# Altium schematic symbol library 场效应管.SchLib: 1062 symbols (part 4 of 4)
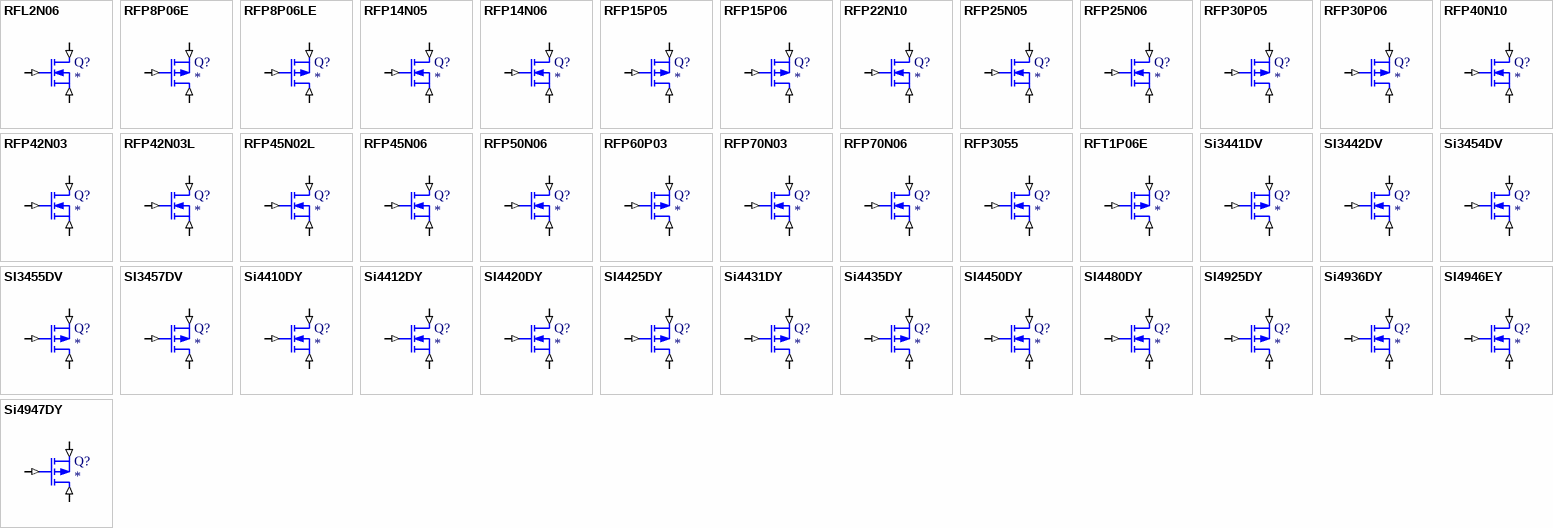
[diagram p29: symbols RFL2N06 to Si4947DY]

## RFP3055
designator Q?
N-Channel MOSFET
simulation model RFP3055 (SUBCKT)
pins: 1 D (in), 2 G (in), 3 S (in)
1 alternate drawing of the same symbol

## RFT1P06E
designator Q?
P-Channel MOSFET
simulation model RFT1P06E (SUBCKT)
pins: 1 D (in), 2 G (in), 3 S (in)
1 alternate drawing of the same symbol

## Si3441DV
designator Q?
P-Channel MOSFET
simulation model Si3441DV (SUBCKT)
pins: 1 D (in), 2 G (in), 3 S (in)
1 alternate drawing of the same symbol

## SI3442DV
designator Q?
N-Channel MOSFET
simulation model SI3442DV (SUBCKT)
pins: 1 D (in), 2 G (in), 3 S (in)
1 alternate drawing of the same symbol

## Si3454DV
designator Q?
N-Channel MOSFET
simulation model Si3454DV (SUBCKT)
pins: 1 D (in), 2 G (in), 3 S (in)
1 alternate drawing of the same symbol

## SI3455DV
designator Q?
P-Channel MOSFET
simulation model SI3455DV (SUBCKT)
pins: 1 D (in), 2 G (in), 3 S (in)
1 alternate drawing of the same symbol

## SI3457DV
designator Q?
P-Channel MOSFET
simulation model SI3457DV (SUBCKT)
pins: 1 D (in), 2 G (in), 3 S (in)
1 alternate drawing of the same symbol

## Si4410DY
designator Q?
N-Channel MOSFET
simulation model Si4410DY (SUBCKT)
pins: 1 D (in), 2 G (in), 3 S (in)
1 alternate drawing of the same symbol

## Si4412DY
designator Q?
N-Channel MOSFET
simulation model Si4412DY (SUBCKT)
pins: 1 D (in), 2 G (in), 3 S (in)
1 alternate drawing of the same symbol

## SI4420DY
designator Q?
N-Channel MOSFET
simulation model SI4420DY (SUBCKT)
pins: 1 D (in), 2 G (in), 3 S (in)
1 alternate drawing of the same symbol

## SI4425DY
designator Q?
P-Channel MOSFET
simulation model SI4425DY (SUBCKT)
pins: 1 D (in), 2 G (in), 3 S (in)
1 alternate drawing of the same symbol

## Si4431DY
designator Q?
P-Channel MOSFET
simulation model Si4431DY (SUBCKT)
pins: 1 D (in), 2 G (in), 3 S (in)
1 alternate drawing of the same symbol

## Si4435DY
designator Q?
P-Channel MOSFET
simulation model Si4435DY (SUBCKT)
pins: 1 D (in), 2 G (in), 3 S (in)
1 alternate drawing of the same symbol

## SI4450DY
designator Q?
N-Channel MOSFET
simulation model SI4450DY (SUBCKT)
pins: 1 D (in), 2 G (in), 3 S (in)
1 alternate drawing of the same symbol

## SI4480DY
designator Q?
N-Channel MOSFET
simulation model SI4480DY (SUBCKT)
pins: 1 D (in), 2 G (in), 3 S (in)
1 alternate drawing of the same symbol

## SI4925DY
designator Q?
P-Channel MOSFET
simulation model SI4925DY (SUBCKT)
pins: 1 D (in), 2 G (in), 3 S (in)
1 alternate drawing of the same symbol

## Si4936DY
designator Q?
N-Channel MOSFET
simulation model Si4936DY (SUBCKT)
pins: 1 D (in), 2 G (in), 3 S (in)
1 alternate drawing of the same symbol

## SI4946EY
designator Q?
N-Channel MOSFET
simulation model SI4946EY (SUBCKT)
pins: 1 D (in), 2 G (in), 3 S (in)
1 alternate drawing of the same symbol

## Si4947DY
designator Q?
P-Channel MOSFET
simulation model Si4947DY (SUBCKT)
pins: 1 D (in), 2 G (in), 3 S (in)
1 alternate drawing of the same symbol

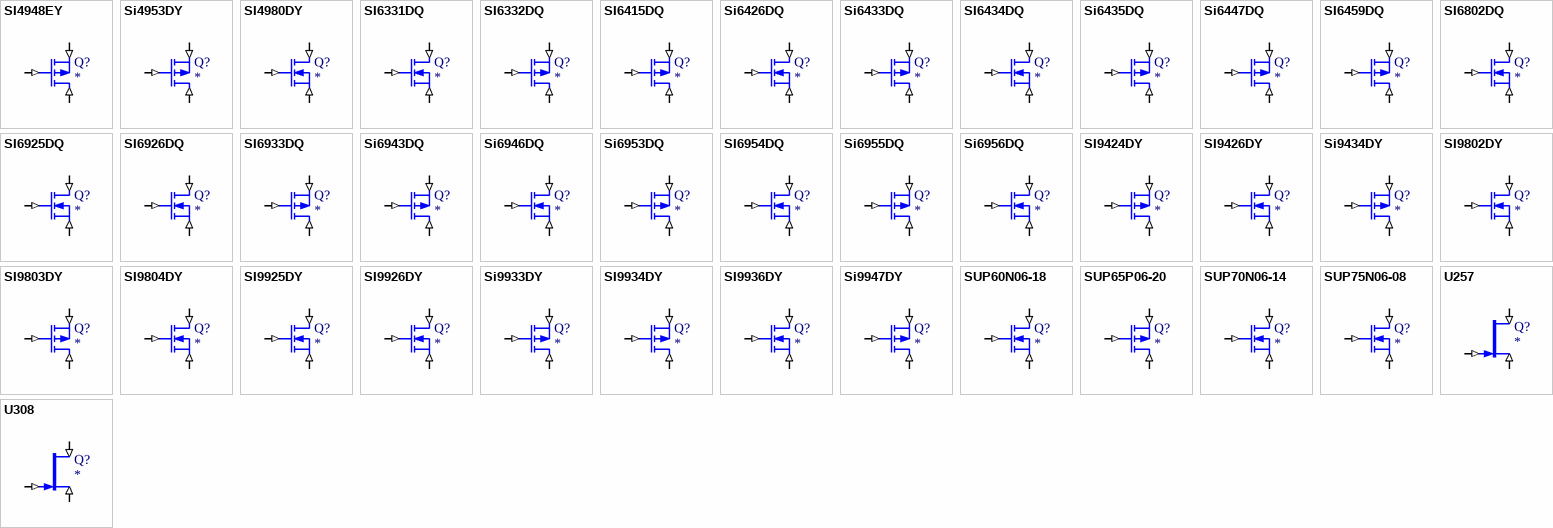
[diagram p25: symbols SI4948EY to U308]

## SI4948EY
designator Q?
P-Channel MOSFET
simulation model SI4948EY (SUBCKT)
pins: 1 D (in), 2 G (in), 3 S (in)
1 alternate drawing of the same symbol

## Si4953DY
designator Q?
P-Channel MOSFET
simulation model Si4953DY (SUBCKT)
pins: 1 D (in), 2 G (in), 3 S (in)
1 alternate drawing of the same symbol

## SI4980DY
designator Q?
N-Channel MOSFET
simulation model SI4980DY (SUBCKT)
pins: 1 D (in), 2 G (in), 3 S (in)
1 alternate drawing of the same symbol

## SI6331DQ
designator Q?
N-Channel MOSFET
simulation model SI6331DQ (SUBCKT)
pins: 1 D (in), 2 G (in), 3 S (in)
1 alternate drawing of the same symbol

## SI6332DQ
designator Q?
P-Channel MOSFET
simulation model SI6332DQ (SUBCKT)
pins: 1 D (in), 2 G (in), 3 S (in)
1 alternate drawing of the same symbol

## SI6415DQ
designator Q?
P-Channel MOSFET
simulation model SI6415DQ (SUBCKT)
pins: 1 D (in), 2 G (in), 3 S (in)
1 alternate drawing of the same symbol

## Si6426DQ
designator Q?
N-Channel MOSFET
simulation model Si6426DQ (SUBCKT)
pins: 1 D (in), 2 G (in), 3 S (in)
1 alternate drawing of the same symbol

## Si6433DQ
designator Q?
P-Channel MOSFET
simulation model Si6433DQ (SUBCKT)
pins: 1 D (in), 2 G (in), 3 S (in)
1 alternate drawing of the same symbol

## SI6434DQ
designator Q?
N-Channel MOSFET
simulation model SI6434DQ (SUBCKT)
pins: 1 D (in), 2 G (in), 3 S (in)
1 alternate drawing of the same symbol

## Si6435DQ
designator Q?
P-Channel MOSFET
simulation model Si6435DQ (SUBCKT)
pins: 1 D (in), 2 G (in), 3 S (in)
1 alternate drawing of the same symbol

## Si6447DQ
designator Q?
P-Channel MOSFET
simulation model Si6447DQ (SUBCKT)
pins: 1 D (in), 2 G (in), 3 S (in)
1 alternate drawing of the same symbol

## SI6459DQ
designator Q?
P-Channel MOSFET
simulation model SI6459DQ (SUBCKT)
pins: 1 D (in), 2 G (in), 3 S (in)
1 alternate drawing of the same symbol

## SI6802DQ
designator Q?
N-Channel MOSFET
simulation model SI6802DQ (SUBCKT)
pins: 1 D (in), 2 G (in), 3 S (in)
1 alternate drawing of the same symbol

## SI6925DQ
designator Q?
N-Channel MOSFET
simulation model SI6925DQ (SUBCKT)
pins: 1 D (in), 2 G (in), 3 S (in)
1 alternate drawing of the same symbol

## SI6926DQ
designator Q?
N-Channel MOSFET
simulation model SI6926DQ (SUBCKT)
pins: 1 D (in), 2 G (in), 3 S (in)
1 alternate drawing of the same symbol

## SI6933DQ
designator Q?
P-Channel MOSFET
simulation model SI6933DQ (SUBCKT)
pins: 1 D (in), 2 G (in), 3 S (in)
1 alternate drawing of the same symbol

## Si6943DQ
designator Q?
P-Channel MOSFET
simulation model Si6943DQ (SUBCKT)
pins: 1 D (in), 2 G (in), 3 S (in)
1 alternate drawing of the same symbol

## Si6946DQ
designator Q?
N-Channel MOSFET
simulation model Si6946DQ (SUBCKT)
pins: 1 D (in), 2 G (in), 3 S (in)
1 alternate drawing of the same symbol

## Si6953DQ
designator Q?
P-Channel MOSFET
simulation model Si6953DQ (SUBCKT)
pins: 1 D (in), 2 G (in), 3 S (in)
1 alternate drawing of the same symbol

## SI6954DQ
designator Q?
N-Channel MOSFET
simulation model SI6954DQ (SUBCKT)
pins: 1 D (in), 2 G (in), 3 S (in)
1 alternate drawing of the same symbol

## Si6955DQ
designator Q?
P-Channel MOSFET
simulation model Si6955DQ (SUBCKT)
pins: 1 D (in), 2 G (in), 3 S (in)
1 alternate drawing of the same symbol

## Si6956DQ
designator Q?
N-Channel MOSFET
simulation model Si6956DQ (SUBCKT)
pins: 1 D (in), 2 G (in), 3 S (in)
1 alternate drawing of the same symbol

## SI9424DY
designator Q?
P-Channel MOSFET
simulation model SI9424DY (SUBCKT)
pins: 1 D (in), 2 G (in), 3 S (in)
1 alternate drawing of the same symbol

## SI9426DY
designator Q?
N-Channel MOSFET
simulation model SI9426DY (SUBCKT)
pins: 1 D (in), 2 G (in), 3 S (in)
1 alternate drawing of the same symbol

## Si9434DY
designator Q?
P-Channel MOSFET
simulation model Si9434DY (SUBCKT)
pins: 1 D (in), 2 G (in), 3 S (in)
1 alternate drawing of the same symbol

## SI9802DY
designator Q?
N-Channel MOSFET
simulation model SI9802DY (SUBCKT)
pins: 1 D (in), 2 G (in), 3 S (in)
1 alternate drawing of the same symbol

## SI9803DY
designator Q?
P-Channel MOSFET
simulation model SI9803DY (SUBCKT)
pins: 1 D (in), 2 G (in), 3 S (in)
1 alternate drawing of the same symbol

## SI9804DY
designator Q?
N-Channel MOSFET
simulation model SI9804DY (SUBCKT)
pins: 1 D (in), 2 G (in), 3 S (in)
1 alternate drawing of the same symbol

## SI9925DY
designator Q?
N-Channel MOSFET
simulation model SI9925DY (SUBCKT)
pins: 1 D (in), 2 G (in), 3 S (in)
1 alternate drawing of the same symbol

## SI9926DY
designator Q?
N-Channel MOSFET
simulation model SI9926DY (SUBCKT)
pins: 1 D (in), 2 G (in), 3 S (in)
1 alternate drawing of the same symbol

## Si9933DY
designator Q?
P-Channel MOSFET
simulation model Si9933DY (SUBCKT)
pins: 1 D (in), 2 G (in), 3 S (in)
1 alternate drawing of the same symbol

## SI9934DY
designator Q?
P-Channel MOSFET
simulation model SI9934DY (SUBCKT)
pins: 1 D (in), 2 G (in), 3 S (in)
1 alternate drawing of the same symbol

## SI9936DY
designator Q?
N-Channel MOSFET
simulation model SI9936DY (SUBCKT)
pins: 1 D (in), 2 G (in), 3 S (in)
1 alternate drawing of the same symbol

## Si9947DY
designator Q?
P-Channel MOSFET
simulation model Si9947DY (SUBCKT)
pins: 1 D (in), 2 G (in), 3 S (in)
1 alternate drawing of the same symbol

## SUP60N06-18
designator Q?
N-Channel MOSFET
simulation model SUP60N06-18 (SUBCKT)
pins: 1 D (in), 2 G (in), 3 S (in)
1 alternate drawing of the same symbol

## SUP65P06-20
designator Q?
P-Channel MOSFET
simulation model SUP65P06-20 (SUBCKT)
pins: 1 D (in), 2 G (in), 3 S (in)
1 alternate drawing of the same symbol

## SUP70N06-14
designator Q?
N-Channel MOSFET
simulation model SUP70N06-14 (SUBCKT)
pins: 1 D (in), 2 G (in), 3 S (in)
1 alternate drawing of the same symbol

## SUP75N06-08
designator Q?
N-Channel MOSFET
simulation model SUP75N06-08 (SUBCKT)
pins: 1 D (in), 2 G (in), 3 S (in)
1 alternate drawing of the same symbol

## U257
designator Q?
N-Channel JFET
simulation model U257 (NJFET)
pins: 1 D (in), 2 G (in), 3 S (in)
1 alternate drawing of the same symbol

## U308
designator Q?
N-Channel JFET
simulation model U308 (NJFET)
pins: 1 D (in), 2 G (in), 3 S (in)
1 alternate drawing of the same symbol

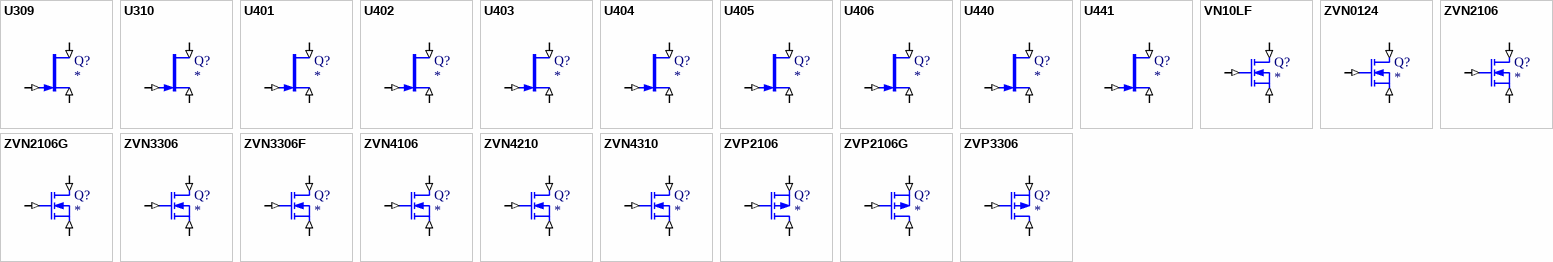
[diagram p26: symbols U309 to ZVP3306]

## U309
designator Q?
N-Channel JFET
simulation model U309 (NJFET)
pins: 1 D (in), 2 G (in), 3 S (in)
1 alternate drawing of the same symbol

## U310
designator Q?
N-Channel JFET
simulation model U310 (NJFET)
pins: 1 D (in), 2 G (in), 3 S (in)
1 alternate drawing of the same symbol

## U401
designator Q?
N-Channel JFET
simulation model U401 (NJFET)
pins: 1 D (in), 2 G (in), 3 S (in)
1 alternate drawing of the same symbol

## U402
designator Q?
N-Channel JFET
simulation model U402 (NJFET)
pins: 1 D (in), 2 G (in), 3 S (in)
1 alternate drawing of the same symbol

## U403
designator Q?
N-Channel JFET
simulation model U403 (NJFET)
pins: 1 D (in), 2 G (in), 3 S (in)
1 alternate drawing of the same symbol

## U404
designator Q?
N-Channel JFET
simulation model U404 (NJFET)
pins: 1 D (in), 2 G (in), 3 S (in)
1 alternate drawing of the same symbol

## U405
designator Q?
N-Channel JFET
simulation model U405 (NJFET)
pins: 1 D (in), 2 G (in), 3 S (in)
1 alternate drawing of the same symbol

## U406
designator Q?
N-Channel JFET
simulation model U406 (NJFET)
pins: 1 D (in), 2 G (in), 3 S (in)
1 alternate drawing of the same symbol

## U440
designator Q?
N-Channel JFET
simulation model U440 (NJFET)
pins: 1 D (in), 2 G (in), 3 S (in)
1 alternate drawing of the same symbol

## U441
designator Q?
N-Channel JFET
simulation model U441 (NJFET)
pins: 1 D (in), 2 G (in), 3 S (in)
1 alternate drawing of the same symbol

## VN10LF
designator Q?
N-Channel MOSFET
simulation model VN10LF (SUBCKT)
pins: 1 D (in), 2 G (in), 3 S (in)
1 alternate drawing of the same symbol

## ZVN0124
designator Q?
N-Channel MOSFET
simulation model ZVN0124 (SUBCKT)
pins: 1 D (in), 2 G (in), 3 S (in)
1 alternate drawing of the same symbol

## ZVN2106
designator Q?
N-Channel MOSFET
simulation model ZVN2106 (SUBCKT)
pins: 1 D (in), 2 G (in), 3 S (in)
1 alternate drawing of the same symbol

## ZVN2106G
designator Q?
N-Channel MOSFET
simulation model ZVN2106G (SUBCKT)
pins: 1 D (in), 2 G (in), 3 S (in)
1 alternate drawing of the same symbol

## ZVN3306
designator Q?
N-Channel MOSFET
simulation model ZVN3306 (SUBCKT)
pins: 1 D (in), 2 G (in), 3 S (in)
1 alternate drawing of the same symbol

## ZVN3306F
designator Q?
N-Channel MOSFET
simulation model ZVN3306F (SUBCKT)
pins: 1 D (in), 2 G (in), 3 S (in)
1 alternate drawing of the same symbol

## ZVN4106
designator Q?
N-Channel MOSFET
simulation model ZVN4106 (SUBCKT)
pins: 1 D (in), 2 G (in), 3 S (in)
1 alternate drawing of the same symbol

## ZVN4210
designator Q?
N-Channel MOSFET
simulation model ZVN4210 (SUBCKT)
pins: 1 D (in), 2 G (in), 3 S (in)
1 alternate drawing of the same symbol

## ZVN4310
designator Q?
N-Channel MOSFET
simulation model ZVN4310 (SUBCKT)
pins: 1 D (in), 2 G (in), 3 S (in)
1 alternate drawing of the same symbol

## ZVP2106
designator Q?
P-Channel MOSFET
simulation model ZVP2106 (SUBCKT)
pins: 1 D (in), 2 G (in), 3 S (in)
1 alternate drawing of the same symbol

## ZVP2106G
designator Q?
P-Channel MOSFET
simulation model ZVP2106G (SUBCKT)
pins: 1 D (in), 2 G (in), 3 S (in)
1 alternate drawing of the same symbol

## ZVP3306
designator Q?
P-Channel MOSFET
simulation model ZVP3306 (SUBCKT)
pins: 1 D (in), 2 G (in), 3 S (in)
1 alternate drawing of the same symbol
